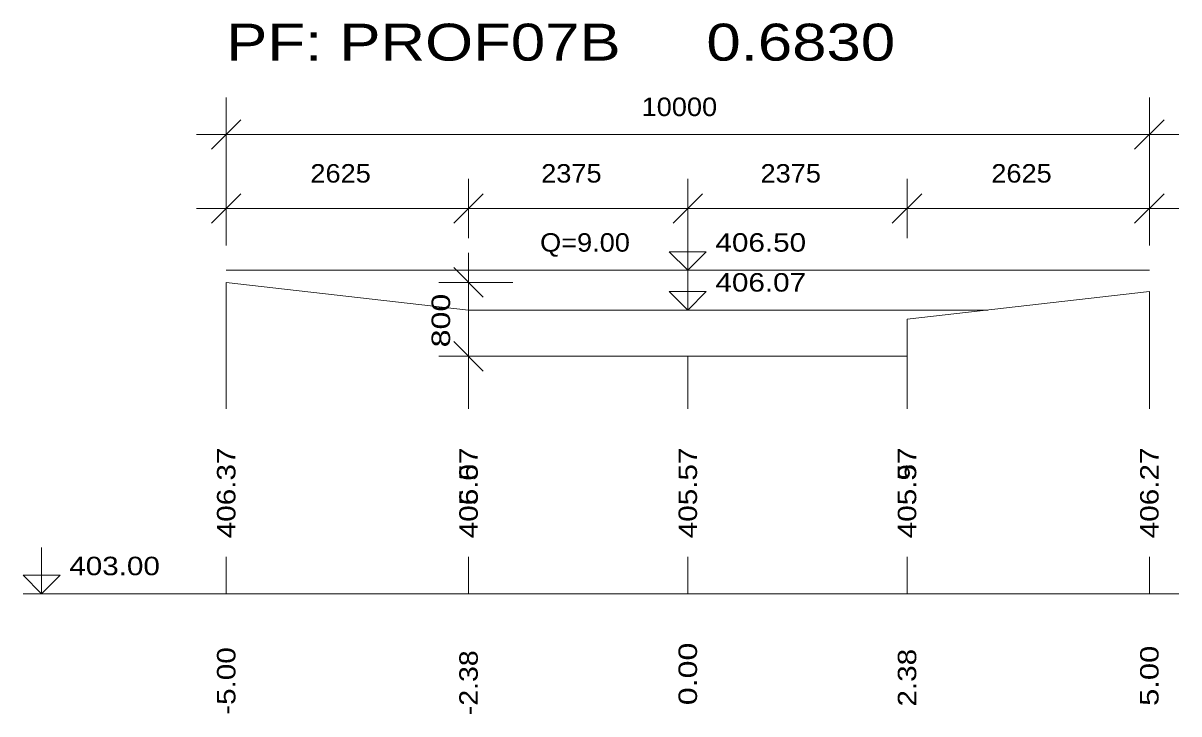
# Model space of a CAD drawing. Extents: x 7 to 442, y -393 to 441.
# Drawn here: x 294.44 to 306.95, y -30.1 to -22.62 of the extents above; entities that cross this region are included whole.
import ezdxf

# ---------------------------------------------------------------- set-up
doc = ezdxf.new("R2010")
doc.units = 0
doc.header["$LTSCALE"] = 0.08
doc.layers.add('7', color=7, linetype='Continuous', lineweight=13)

msp = doc.modelspace()

# ---------------------------------------------------------------- linework, layer by layer
at = {"layer": '7'}
for p, q in [((296.635, -25.03), (296.635, -23.43)), ((306.635, -25.03), (306.635, -23.43)), ((296.475, -23.99), (296.795, -23.67)), ((306.475, -23.99), (306.795, -23.67)), ((296.315, -23.83), (306.955, -23.83)), ((296.635, -24.95), (296.635, -24.31)), ((299.26, -24.95), (299.26, -24.31)), ((299.26, -24.95), (299.26, -24.31)), ((301.635, -24.95), (301.635, -24.31)), ((304.01, -24.95), (304.01, -24.31)), ((304.01, -24.95), (304.01, -24.31)), ((306.635, -24.95), (306.635, -24.31)), ((296.475, -24.79), (296.795, -24.47)), ((299.1, -24.79), (299.42, -24.47)), ((299.1, -24.79), (299.42, -24.47)), ((301.475, -24.79), (301.795, -24.47)), ((303.85, -24.79), (304.17, -24.47)), ((303.85, -24.79), (304.17, -24.47)), ((306.475, -24.79), (306.795, -24.47)), ((296.315, -24.63), (306.955, -24.63)), ((299.26, -26.39), (299.26, -25.11)), ((299.42, -25.59), (299.1, -25.27)), ((296.635, -25.298), (306.635, -25.298)), ((296.635, -26.8), (296.635, -25.43)), ((298.94, -25.43), (299.74, -25.43)), ((306.635, -26.8), (306.635, -25.53)), ((299.26, -26.8), (299.26, -25.73)), ((299.26, -25.73), (304.885, -25.73)), ((304.01, -26.8), (304.01, -25.83)), ((299.42, -26.39), (299.1, -26.07)), ((298.94, -26.23), (299.74, -26.23)), ((299.26, -26.8), (299.26, -26.23)), ((301.635, -26.8), (301.635, -26.23)), ((304.01, -26.8), (304.01, -26.23)), ((296.635, -28.8), (296.635, -28.4)), ((299.26, -28.8), (299.26, -28.4)), ((299.26, -28.8), (299.26, -28.4)), ((301.635, -28.8), (301.635, -28.4)), ((304.01, -28.8), (304.01, -28.4)), ((304.01, -28.8), (304.01, -28.4)), ((306.635, -28.8), (306.635, -28.4)), ((294.435, -28.8), (306.955, -28.8))]:
    msp.add_line(p, q, dxfattribs=at)
for points in [[(301.635, -24.798), (301.635, -25.298), (301.435, -25.098), (301.835, -25.098), (301.635, -25.298)], [(301.635, -25.23), (301.635, -25.73), (301.435, -25.53), (301.835, -25.53), (301.635, -25.73)], [(296.635, -25.43), (299.26, -25.73), (299.26, -26.23), (301.635, -26.23), (304.01, -26.23), (304.01, -25.83), (306.635, -25.53)], [(294.635, -28.3), (294.635, -28.8), (294.435, -28.6), (294.835, -28.6), (294.635, -28.8)]]:
    msp.add_lwpolyline(points, dxfattribs=at)

# ---------------------------------------------------------------- texts
for s, height, width, p in [('PF: PROF07B     0.6830', 0.4, 1.25, (296.635, -23.03)), ('10000', 0.2, 1.1, (301.135, -23.63)), ('2625', 0.2, 1.1, (297.547, -24.35)), ('2375', 0.2, 1.1, (300.047, -24.35)), ('2375', 0.2, 1.1, (302.423, -24.35)), ('2625', 0.2, 1.1, (304.923, -24.35)), ('Q=9.00', 0.2, 1.1, (300.035, -25.098)), ('406.50', 0.2, 1.2, (301.935, -25.098)), ('406.07', 0.2, 1.2, (301.935, -25.53)), ('403.00', 0.2, 1.2, (294.935, -28.6))]:
    msp.add_text(s, height=height, dxfattribs=dict(at, width=width)).set_placement(p)
for s, width, p in [(' 800', 1.3, (299.06, -26.23)), ('406.37 ', 1.2, (296.735, -28.2)), ('406.07 ', 1.2, (299.36, -28.2)), ('405.57 ', 1.2, (299.36, -28.2)), ('405.57 ', 1.2, (301.735, -28.2)), ('405.57 ', 1.2, (304.11, -28.2)), ('405.97 ', 1.2, (304.11, -28.2)), ('406.27 ', 1.2, (306.735, -28.2)), (' -5.00 ', 1.2, (296.735, -30.2)), ('  0.00 ', 1.3, (301.735, -30.2)), ('  2.38 ', 1.2, (304.11, -30.2)), ('  2.38 ', 1.2, (304.11, -30.2)), ('  5.00 ', 1.25, (306.735, -30.2)), (' -2.38 ', 1.15, (299.36, -30.2)), (' -2.38 ', 1.15, (299.36, -30.2))]:
    msp.add_text(s, height=0.2, rotation=90, dxfattribs=dict(at, width=width)).set_placement(p)

doc.saveas('drawing.dxf')
